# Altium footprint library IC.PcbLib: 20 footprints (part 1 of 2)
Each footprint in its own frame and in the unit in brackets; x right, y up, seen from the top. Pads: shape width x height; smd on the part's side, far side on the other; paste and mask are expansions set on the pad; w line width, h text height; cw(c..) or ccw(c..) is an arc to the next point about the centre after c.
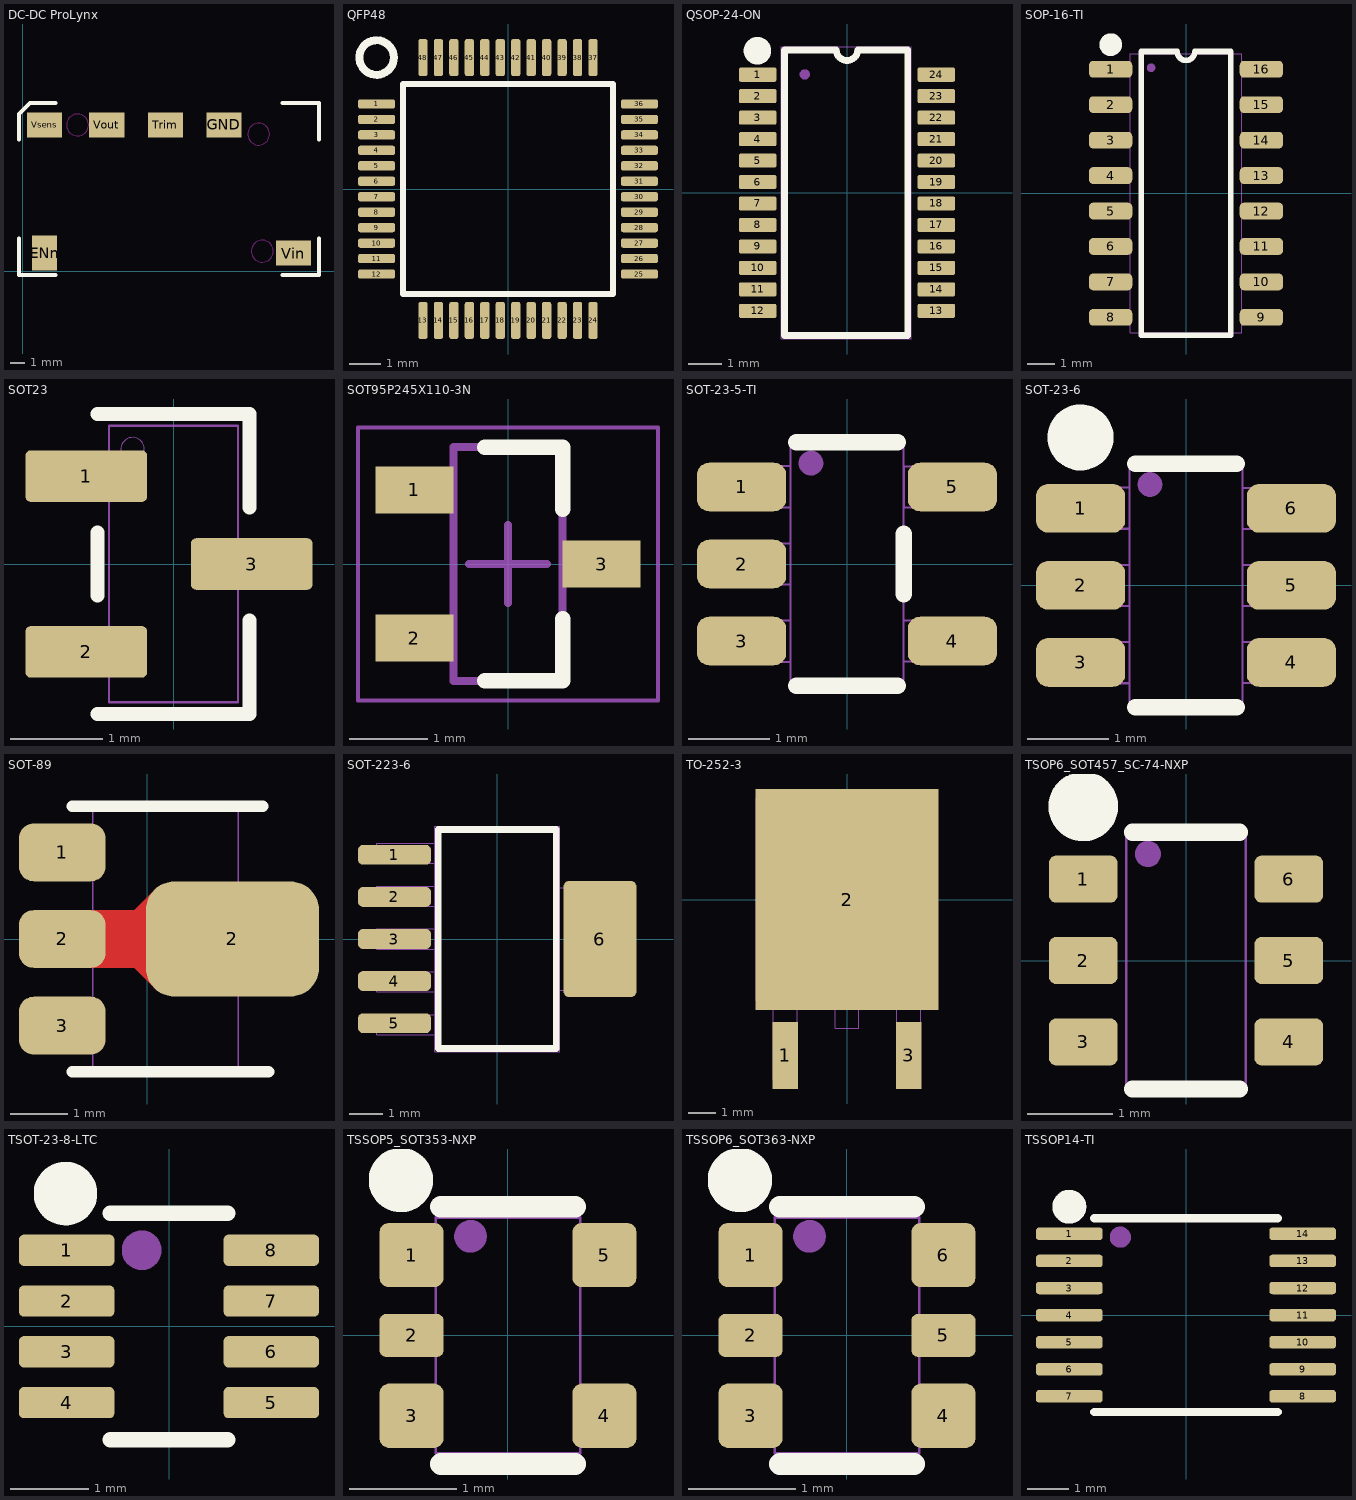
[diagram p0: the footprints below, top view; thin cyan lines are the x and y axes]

## DC-DC ProLynx [mil]
pads (6):
  rect 68x96 smd: ENn(60,50)
  rect 96x68 smd: GND(550,400) Trim(390,400) Vin(740,50) Vout(230,400) Vsens(60,400)
Top Layer keep-out:
  circle w1: c645,375 r30
  circle w1: c655,55 r30
  circle w1: c150,400 r30
Top Overlay:
  lines w10: -10,90 -10,-10 90,-10 ; -10,360 -10,430 20,460 90,460 ; 710,-10 810,-10 810,90 ; 710,460 810,460 810,360

## QFP48 [mm]
pads (48):
  rrect50% 1.2x0.3 smd mask+0.051: 1(-4.25,2.75) 2(-4.25,2.25) 3(-4.25,1.75) 4(-4.25,1.25) 5(-4.25,0.75) 6(-4.25,0.25) 7(-4.25,-0.25) 8(-4.25,-0.75) 9(-4.25,-1.25) 10(-4.25,-1.75) 11(-4.25,-2.25) 12(-4.25,-2.75) 25(4.25,-2.75) 26(4.25,-2.25) 27(4.25,-1.75) 28(4.25,-1.25) 29(4.25,-0.75) 30(4.25,-0.25) 31(4.25,0.25) 32(4.25,0.75) 33(4.25,1.25) 34(4.25,1.75) 35(4.25,2.25) 36(4.25,2.75)
  rrect50% 0.3x1.2 smd mask+0.051: 13(-2.75,-4.25) 14(-2.25,-4.25) 15(-1.75,-4.25) 16(-1.25,-4.25) 17(-0.75,-4.25) 18(-0.25,-4.25) 19(0.25,-4.25) 20(0.75,-4.25) 21(1.25,-4.25) 22(1.75,-4.25) 23(2.25,-4.25) 24(2.75,-4.25) 37(2.75,4.25) 38(2.25,4.25) 39(1.75,4.25) 40(1.25,4.25) 41(0.75,4.25) 42(0.25,4.25) 43(-0.25,4.25) 44(-0.75,4.25) 45(-1.25,4.25) 46(-1.75,4.25) 47(-2.25,4.25) 48(-2.75,4.25)
Top Overlay:
  circle w0.254: c-4.25,4.25 r0.559
  lines w0.2: -3.4,-3.4 -3.4,3.4 3.4,3.4 3.4,-3.4 -3.4,-3.4

## QSOP-24-ON [mm]
pads (24):
  rrect30% 1.12x0.42 smd mask+0.05: 1(-2.64,3.492) 2(-2.64,2.857) 3(-2.64,2.222) 4(-2.64,1.587) 5(-2.64,0.953) 6(-2.64,0.318) 7(-2.64,-0.318) 8(-2.64,-0.953) 9(-2.64,-1.587) 10(-2.64,-2.222) 11(-2.64,-2.857) 12(-2.64,-3.492) 13(2.64,-3.492) 14(2.64,-2.857) 15(2.64,-2.222) 16(2.64,-1.587) 17(2.64,-0.953) 18(2.64,-0.318) 19(2.64,0.318) 20(2.64,0.953) 21(2.64,1.587) 22(2.64,2.222) 23(2.64,2.857) 24(2.64,3.492)
Top Overlay:
  circle w0.406: c-2.65,4.2 r0.203
  lines w0.2: -0.325,4.225 -1.85,4.225 -1.85,-4.225 1.8,-4.225 1.8,4.225 0.325,4.225 ; -0.318,4.23 ccw(c0,4.23) 0.318,4.23
Mechanical 13:
  circle w0.152: c-1.25,3.5 r0.076
  lines w0.025: -1.95,-4.325 1.9,-4.325 1.9,4.325 -1.95,4.325 -1.95,-4.325
  text ".Designator" at -0.275,3.6 h0.76

## SOP-16-TI [mm]
pads (16):
  rrect50% 1.55x0.6 smd: 1(-2.7,4.445) 2(-2.7,3.175) 3(-2.7,1.905) 4(-2.7,0.635) 5(-2.7,-0.635) 6(-2.7,-1.905) 7(-2.7,-3.175) 8(-2.7,-4.445) 9(2.7,-4.445) 10(2.7,-3.175) 11(2.7,-1.905) 12(2.7,-0.635) 13(2.7,0.635) 14(2.7,1.905) 15(2.7,3.175) 16(2.7,4.445)
Top Overlay:
  circle w0.406: c-2.7,5.325 r0.203
  lines w0.2: -1.6,-5.08 1.6,-5.08 1.6,5.08 0.318,5.08 cw(c0,5.08) -0.318,5.08 -1.6,5.08 -1.6,-5.08
Mechanical 13:
  circle w0.152: c-1.25,4.5 r0.076
  lines w0.025: -2,-5 -2,5 2,5 2,-5 -2,-5
  text ".Designator" at -0.25,4.5 h0.76

## SOT23 [mil]
pads (3):
  rrect20% 52x22 smd paste+0 mask+0: 1(-37.21,37.5) 2(-37.21,-37.5) 3(33.36,0)
Top Overlay:
  lines w6: -32.5,-64 32.5,-64 32.5,-24.1 ; -32.5,-13.4 -32.5,13.4 ; -32.5,64 32.5,64 32.5,24.1
Mechanical 13:
  circle w0: c-17.5,49 r5
  lines w1: -49.21,-47.5 -27.5,-47.5 -27.5,-27.5 -49.21,-27.5 -49.21,-47.5 ; -49.21,27.5 -27.5,27.5 -27.5,47.5 -49.21,47.5 -49.21,27.5 ; -27.5,-59 27.5,-59 27.5,59 -27.5,59 -27.5,-59 ; 27.5,-10 49.21,-10 49.21,10 27.5,10 27.5,-10
  text ".Designator" at -14,54 h30

## SOT95P245X110-3N [mm] "SOT23, 3-Leads, Body 2.90x2.45mm, Pitch 0.95mm, IPC Medium Density"
height 1.1
pads (3):
  rect 1x0.6 smd: 1(-1.2,0.95) 2(-1.2,-0.95) 3(1.2,0)
Top Overlay:
  lines w0.2: -0.3,-1.5 0.7,-1.5 0.7,-0.7 ; -0.3,1.5 0.7,1.5 0.7,0.7
Mechanical 13:
  lines w0.1: -0.7,-1.5 -0.7,1.5 0.7,1.5 0.7,-1.5 -0.7,-1.5
Mechanical 15:
  lines w0.05: -1.925,-1.75 -1.925,1.75 1.925,1.75 1.925,-1.75 -1.925,-1.75
  lines w0.1: -0.5,0 0.5,0 ; 0,-0.5 0,0.5
3D body: height 1.1, standoff 0.05, extent -0.7,-1.5 0.7,1.5

## SOT-23-5-TI [mm]
pads (5):
  rrect50% 1.1x0.6 smd: 1(-1.3,0.95) 2(-1.3,0) 3(-1.3,-0.95) 4(1.3,-0.95) 5(1.3,0.95)
Top Overlay:
  lines w0.203: -0.625,-1.5 0.625,-1.5 ; -0.625,1.5 0.625,1.5 ; 0.7,-0.375 0.7,0.375
Mechanical 13:
  circle w0.152: c-0.445,1.245 r0.076
  lines w0.025: -1.25,-1.206 -0.699,-1.206 -0.699,-0.699 -1.25,-0.699 -1.25,-1.206 ; -1.25,-0.254 -1.25,0.254 -0.699,0.254 -0.699,-0.254 -1.25,-0.254 ; -1.25,0.699 -0.699,0.699 -0.699,1.206 -1.25,1.206 -1.25,0.699 ; -0.699,-1.499 0.699,-1.499 0.699,1.499 -0.699,1.499 -0.699,-1.499 ; 0.699,-1.204 0.699,-0.696 1.25,-0.696 1.25,-1.204 0.699,-1.204 ; 0.7,0.696 0.7,1.204 1.252,1.204 1.252,0.696 0.7,0.696
  text ".Designator" at -0.225,1.1 h0.76

## SOT-23-6 [mm]
height 1.5
pads (6):
  rrect50% 1.1x0.6 smd: 1(-1.3,0.95) 2(-1.3,0) 3(-1.3,-0.95) 4(1.3,-0.95) 5(1.3,0) 6(1.3,0.95)
Top Overlay:
  circle w0.406: c-1.3,1.825 r0.203
  lines w0.203: -0.625,-1.5 0.625,-1.5 ; -0.625,1.5 0.625,1.5
Mechanical 13:
  circle w0.152: c-0.445,1.245 r0.076
  lines w0.025: -0.699,-1.206 -1.25,-1.206 -1.25,-0.699 -0.699,-0.699 ; -0.699,-0.254 -1.25,-0.254 -1.25,0.254 -0.699,0.254 ; -0.699,0.699 -1.25,0.699 -1.25,1.206 -0.699,1.206 ; 0.699,-1.204 1.25,-1.204 1.25,-0.696 0.699,-0.696 ; 0.699,-0.254 1.25,-0.254 1.25,0.254 0.699,0.254 ; 0.7,0.696 1.252,0.696 1.252,1.204 0.7,1.204 ; -0.699,-1.499 0.699,-1.499 0.699,1.499 -0.699,1.499 -0.699,-1.499
  text ".Designator" at -0.225,1.1 h0.76

## SOT-89 [mm]
height 1.5
pads (4):
  rrect50% 1.5x1 smd: 1(-1.474,1.5) 2(-1.474,0) 3(-1.474,-1.5)
  rrect50% 3x2 smd: 2(1.474,0)
Top Layer:
  region: -1.026,0.5 -0.226,0.5 0.174,0.9 0.174,-0.9 -0.226,-0.5 -1.026,-0.5
Top Overlay:
  lines w0.203: -1.3,-2.3 2.1,-2.3 ; -1.3,2.3 2,2.3
Mechanical 13:
  lines w0.025: -0.95,-1.75 -2.05,-1.75 -2.05,-1.25 -0.95,-1.25 ; -0.95,-0.25 -2.05,-0.25 -2.05,0.25 -0.95,0.25 ; -0.95,1.25 -2.05,1.25 -2.05,1.75 -0.95,1.75 ; 1.575,-0.8 2.075,-0.8 2.075,0.8 1.575,0.8 ; -0.95,-2.3 1.575,-2.3 1.575,2.3 -0.95,2.3 -0.95,-2.3
  text ".Designator" at 0.2,2 h1.02

## SOT-223-6 [mm]
pads (6):
  rrect50% 2.2x0.6 smd: 1(-3.1,2.54) 2(-3.1,1.27) 3(-3.1,0) 4(-3.1,-1.27) 5(-3.1,-2.54)
  rrect15% 2.2x3.5 smd: 6(3.1,0)
Top Overlay:
  lines w0.203: -1.778,-3.302 -1.778,3.302 1.778,3.302 1.778,-3.302 -1.778,-3.302
Mechanical 13:
  lines w0.025: -1.88,-2.891 -3.632,-2.891 -3.632,-2.281 -1.88,-2.281 ; -1.88,-1.591 -3.632,-1.591 -3.632,-0.981 -1.88,-0.981 ; -1.88,-0.305 -3.632,-0.305 -3.632,0.305 -1.88,0.305 ; -1.88,0.981 -3.632,0.981 -3.632,1.591 -1.88,1.591 ; -1.88,2.281 -3.632,2.281 -3.632,2.891 -1.88,2.891 ; 1.88,-1.549 3.632,-1.549 3.632,1.549 1.88,1.549 ; -1.88,-3.404 1.88,-3.404 1.88,3.404 -1.88,3.404 -1.88,-3.404
  text ".Designator" at -0.305,2.87 h1.02

## TO-252-3 [mil]
pads (3):
  rect 37x98 smd paste+0 mask+0: 1(-90.16,-227.5) 3(90.16,-227.5)
  rect 267x323 smd paste+0 mask+0: 2(0,0)
Mechanical 13:
  lines w1: -17.5,-147.5 -17.5,-187.5 17.5,-187.5 17.5,-147.5 ; -132.5,-147.5 132.5,-147.5 132.5,147.5 -132.5,147.5 -132.5,-147.5 ; -107.66,-262.5 -107.66,-147.5 -72.66,-147.5 -72.66,-262.5 -107.66,-262.5 ; 72.66,-262.5 72.66,-147.5 107.66,-147.5 107.66,-262.5 72.66,-262.5
  text ".Designator" at -95,-75 h40

## TSOP6_SOT457_SC-74-NXP [mm]
pads (6):
  rrect30% 0.8x0.55 smd: 1(-1.2,0.95) 2(-1.2,0) 3(-1.2,-0.95) 4(1.2,-0.95) 5(1.2,0) 6(1.2,0.95)
Top Overlay:
  circle w0.406: c-1.2,1.8 r0.203
  lines w0.203: -0.625,-1.5 0.625,-1.5 ; -0.625,1.5 0.625,1.5
Mechanical 13:
  circle w0.152: c-0.445,1.245 r0.076
  lines w0.025: -0.699,-1.499 -0.699,1.499 0.699,1.499 0.699,-1.499 -0.699,-1.499
  text ".Designator" at -0.225,1.1 h0.76

## TSOT-23-8-LTC [mm]
pads (8):
  rrect30% 1.22x0.4 smd mask+0.05: 1(-1.31,0.975) 2(-1.31,0.325) 3(-1.31,-0.325) 4(-1.31,-0.975) 5(1.31,-0.975) 6(1.31,-0.325) 7(1.31,0.325) 8(1.31,0.975)
Top Overlay:
  circle w0.406: c-1.325,1.7 r0.203
  lines w0.2: -0.75,-1.45 0.75,-1.45 ; -0.75,1.45 0.75,1.45
Mechanical 13:
  circle w0.254: c-0.35,0.975 r0.127
  text ".Designator" at -0.5,0.8 h1.02

## TSSOP5_SOT353-NXP [mm]
pads (5):
  rrect30% 0.6x0.6 smd mask+0.06: 1(-0.9,0.75) 3(-0.9,-0.75) 4(0.9,-0.75) 5(0.9,0.75)
  rrect30% 0.6x0.4 smd mask+0.06: 2(-0.9,0)
Top Overlay:
  circle w0.3: c-1,1.45 r0.15
  lines w0.203: -0.625,-1.2 0.625,-1.2 ; -0.625,1.2 0.625,1.2
Mechanical 13:
  circle w0.152: c-0.35,0.925 r0.076
  lines w0.025: -0.675,-1.1 -0.675,1.1 0.675,1.1 0.675,-1.1 -0.675,-1.1
  text ".Designator" at -0.275,0.7 h0.6

## TSSOP6_SOT363-NXP [mm]
pads (6):
  rrect30% 0.6x0.6 smd mask+0.06: 1(-0.9,0.75) 3(-0.9,-0.75) 4(0.9,-0.75) 6(0.9,0.75)
  rrect30% 0.6x0.4 smd mask+0.06: 2(-0.9,0) 5(0.9,0)
Top Overlay:
  circle w0.3: c-1,1.45 r0.15
  lines w0.203: -0.625,-1.2 0.625,-1.2 ; -0.625,1.2 0.625,1.2
Mechanical 13:
  circle w0.152: c-0.35,0.925 r0.076
  lines w0.025: -0.675,-1.1 -0.675,1.1 0.675,1.1 0.675,-1.1 -0.675,-1.1
  text ".Designator" at -0.275,0.7 h0.6

## TSSOP14-TI [mm]
pads (14):
  rrect50% 1.6x0.3 smd mask+0.05: 1(-2.8,1.95) 2(-2.8,1.3) 3(-2.8,0.65) 4(-2.8,0) 5(-2.8,-0.65) 6(-2.8,-1.3) 7(-2.8,-1.95) 8(2.8,-1.95) 9(2.8,-1.3) 10(2.8,-0.65) 11(2.8,0) 12(2.8,0.65) 13(2.8,1.3) 14(2.8,1.95)
Top Overlay:
  circle w0.406: c-2.8,2.6 r0.203
  lines w0.2: -2.2,-2.325 2.2,-2.325 ; -2.2,2.325 2.2,2.325
Mechanical 13:
  circle w0.254: c-1.576,1.871 r0.127
  text ".Designator" at -0.4,2.25 h1.02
